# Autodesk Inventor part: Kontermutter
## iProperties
Created: 2006-01
Part Number: Kontermutter
Document SubType Name: Modeling
Designer: Kumpf
Manufacturer: Standard
Standards Organization: Custom
Author: Kumpf
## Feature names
1. Extrusion1
2. Fase1 [Chamfer]
3. Fase2 [Chamfer]
4. Extrusion2
5. Bohrung2 [Hole]
